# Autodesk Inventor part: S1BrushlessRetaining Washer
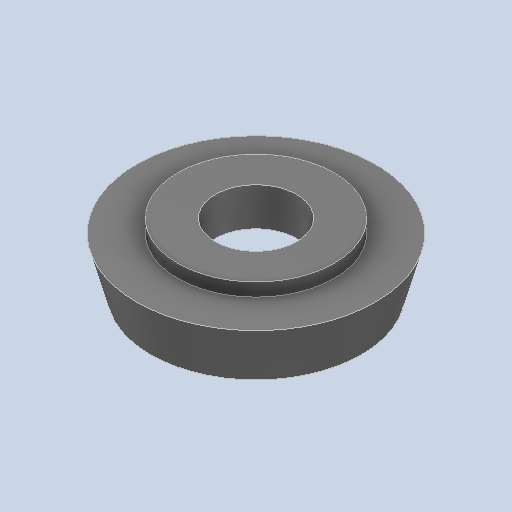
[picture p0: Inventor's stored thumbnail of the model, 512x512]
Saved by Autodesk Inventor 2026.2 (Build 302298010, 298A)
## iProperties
Created: 1601-01
Part Number: S1BrushlessRetaining Washer
Material: Delrin 2700 NC010, Low Viscosity Acetal Copolymer (SS)
Document SubType Name: Modeling
Designer: mel
Density: 1.41 g/cm^3
Appearance: black low gloss plastic
Author: mel
Sending System: SOLIDWORKS 2023
Part Number: Retaining Washer
Last Saved Date: 2025-04-02
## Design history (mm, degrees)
feature "Revolve1"
node "Solide1"
